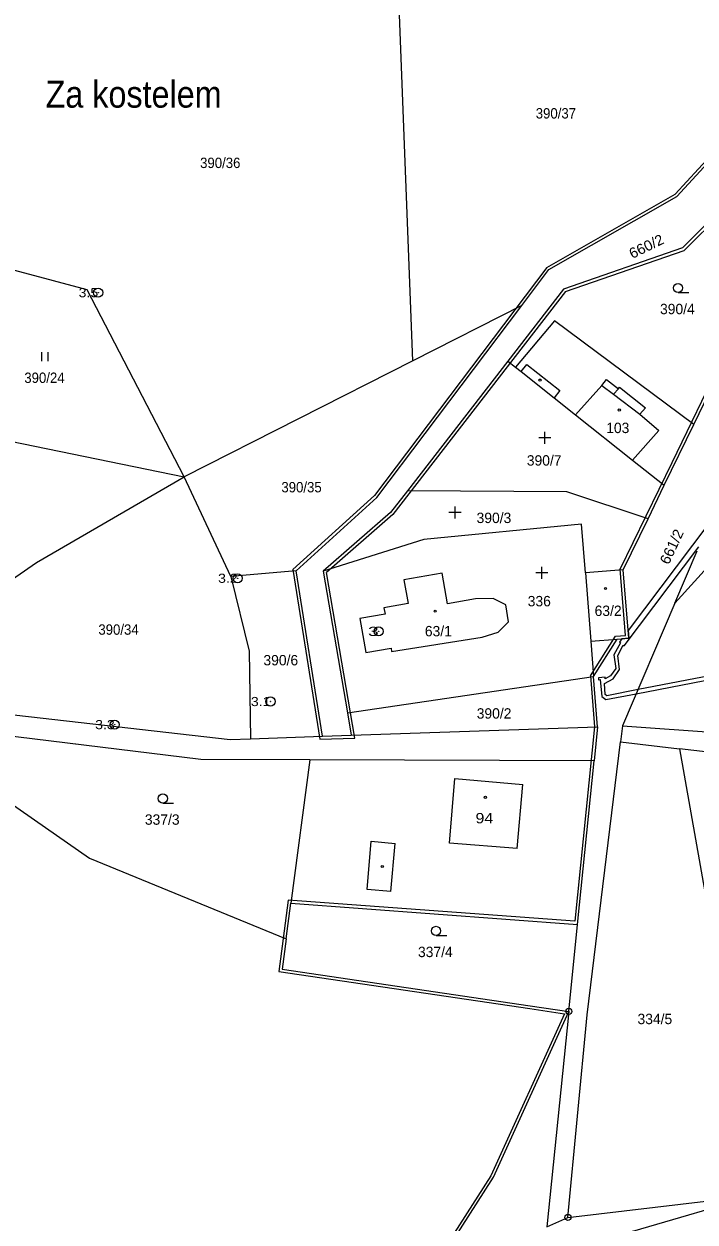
# Model space of a CAD drawing. Extents: x -758887 to -754328, y -1031688 to -1029144.
# Drawn here: x -756703.8 to -756593.9, y -1030846 to -1030649.6 of the extents above; entities that cross this region are included whole.
import ezdxf
from ezdxf.enums import TextEntityAlignment as Align

# ---------------------------------------------------------------- set-up
doc = ezdxf.new("R2010")
doc.units = 0
doc.header["$LTSCALE"] = 0.68
for name, color, linetype, lineweight in [('1', 7, 'Continuous', 25), ('13', 7, 'Continuous', 13), ('3', 7, 'Continuous', 25), ('4', 7, 'Continuous', 13), ('5', 7, 'Continuous', 25), ('7', 7, 'Continuous', 13), ('8', 7, 'Continuous', 25)]:
    doc.layers.add(name, color=color, linetype=linetype, lineweight=lineweight)
doc.layers.add('2', color=7, linetype='Continuous')

msp = doc.modelspace()

# ---------------------------------------------------------------- linework, layer by layer
at = {"layer": '1'}
for p, q in [((-756640.11, -1030704.83), (-756642.87, -1030632.93)), ((-756624.55, -1030704.88), (-756641.02, -1030726.18)), ((-756722.65, -1030714.62), (-756677.61, -1030723.85)), ((-756598.91, -1030725.25), (-756594.09, -1030715.3)), ((-756669.96, -1030740.2), (-756677.61, -1030723.85)), ((-756601.58, -1030730.76), (-756598.91, -1030725.25)), ((-756605.63, -1030739.13), (-756601.58, -1030730.76)), ((-756597.17, -1030744.56), (-756593.53, -1030736.02)), ((-756605.63, -1030739.13), (-756611.84, -1030739.62)), ((-756597.17, -1030744.56), (-756605.74, -1030764.66)), ((-756650.85, -1030762.53), (-756610.49, -1030756.62)), ((-756609.84, -1030764.83), (-756610.49, -1030756.62)), ((-756650.85, -1030762.53), (-756650.22, -1030766.22)), ((-756650.22, -1030766.22), (-756609.84, -1030764.83)), ((-756609.84, -1030764.83), (-756610.4, -1030770.41)), ((-756666.74, -1030766.79), (-756654.94, -1030766.38)), ((-756654.94, -1030766.38), (-756650.22, -1030766.22)), ((-756596.41, -1030768.46), (-756584.22, -1030837.68)), ((-756591.74, -1030769.01), (-756596.41, -1030768.46)), ((-756656.98, -1030770.25), (-756660.11, -1030793.78)), ((-756610.4, -1030770.41), (-756656.98, -1030770.25)), ((-756614.56, -1030811.5), (-756613.12, -1030797.27))]:
    msp.add_line(p, q, dxfattribs=at)
for points in [[(-756622.25, -1030695.77), (-756617.82, -1030689.9), (-756596.84, -1030677.93), (-756567.17, -1030645.53)], [(-756282.9, -1030655.55), (-756308.06, -1030668.02), (-756379, -1030674.01), (-756490.83, -1030676.79), (-756512.76, -1030685.59), (-756531.71, -1030701.08), (-756573.47, -1030723.47), (-756585.94, -1030732.18), (-756597.17, -1030744.56)], [(-756570.62, -1030661.18), (-756595.91, -1030686.32), (-756615.43, -1030693.08), (-756624.55, -1030704.88), (-756623.32, -1030705.86)], [(-756594.09, -1030715.3), (-756580.15, -1030686.52), (-756570.62, -1030661.18)], [(-756677.61, -1030723.85), (-756693.48, -1030693.18), (-756710.9, -1030688.54), (-756722.65, -1030714.62)], [(-756622.25, -1030695.77), (-756640.11, -1030704.83), (-756677.61, -1030723.85)], [(-756659.24, -1030739.27), (-756646.03, -1030727.27), (-756622.25, -1030695.77)], [(-756594.09, -1030715.3), (-756616.91, -1030698.28), (-756623.32, -1030705.86)], [(-756623.32, -1030705.86), (-756622.39, -1030706.6), (-756616.98, -1030710.89), (-756613.46, -1030713.69), (-756604.12, -1030721.11), (-756598.91, -1030725.25)], [(-756722.86, -1030752.48), (-756701.77, -1030737.88), (-756677.61, -1030723.85)], [(-756641.02, -1030726.18), (-756643.76, -1030729.72), (-756654.81, -1030739.33)], [(-756601.58, -1030730.76), (-756614.88, -1030726.31), (-756641.02, -1030726.18)], [(-756611.84, -1030739.62), (-756612.48, -1030731.64), (-756638.34, -1030734.14), (-756654.81, -1030739.33), (-756650.85, -1030762.53)], [(-756654.94, -1030766.38), (-756659.24, -1030739.27), (-756669.96, -1030740.2)], [(-756611.84, -1030739.62), (-756610.95, -1030750.82), (-756610.49, -1030756.62)], [(-756610.49, -1030756.62), (-756606.64, -1030750.47), (-756604.74, -1030750.32), (-756605.63, -1030739.13)], [(-756669.96, -1030740.2), (-756666.92, -1030752.42), (-756666.74, -1030766.79)], [(-756739.59, -1030766.99), (-756715.62, -1030761.72), (-756670.06, -1030766.9), (-756666.74, -1030766.79)], [(-756656.98, -1030770.25), (-756674.86, -1030770.19), (-756715.94, -1030765.19), (-756719.48, -1030766.11)], [(-756605.74, -1030764.66), (-756606.07, -1030767.32), (-756596.41, -1030768.46)], [(-756605.74, -1030764.66), (-756589.65, -1030765.83), (-756579.1, -1030774.93)], [(-756719.48, -1030766.11), (-756711.75, -1030773.45), (-756693.09, -1030786.36), (-756660.88, -1030799.59), (-756660.11, -1030793.78)], [(-756614.71, -1030845.27), (-756611.56, -1030812.04), (-756606.07, -1030767.32)], [(-756660.11, -1030793.78), (-756613.12, -1030797.27), (-756610.4, -1030770.41)], [(-756660.88, -1030799.59), (-756661.54, -1030804.55), (-756620.89, -1030810.56), (-756614.56, -1030811.5)], [(-756672.17, -1030908.07), (-756660.72, -1030891.63), (-756626.91, -1030838.7), (-756614.56, -1030811.5)], [(-756614.56, -1030811.5), (-756618.14, -1030846.79), (-756614.71, -1030845.27)], [(-756614.71, -1030845.27), (-756591.19, -1030842.49), (-756584.22, -1030837.68)], [(-756583.54, -1030841.59), (-756604.14, -1030847.6), (-756617.85, -1030857.11), (-756621.79, -1030861.59), (-756483.51, -1030902.61)]]:
    msp.add_lwpolyline(points, dxfattribs=at)
msp.add_lwpolyline([(-756628.75, -1030750.15), (-756626.15, -1030749.33), (-756624.43, -1030747.61), (-756624.89, -1030744.86), (-756626.95, -1030743.83), (-756629.84, -1030743.88), (-756634.44, -1030744.68), (-756635.32, -1030739.64), (-756641.59, -1030740.73), (-756640.91, -1030744.65), (-756644.85, -1030745.34), (-756644.67, -1030746.39), (-756648.81, -1030747.11), (-756647.84, -1030752.68), (-756643.7, -1030751.96), (-756643.61, -1030752.49)], close=True, dxfattribs=at)
at = {"layer": '13'}
for points in [[(-756591.62, -1030731.54), (-756604.84, -1030749.06), (-756604.74, -1030750.32), (-756605.85, -1030750.41), (-756606.27, -1030750.96), (-756606.11, -1030751.08), (-756607.16, -1030753.02), (-756606.88, -1030755.29), (-756607.72, -1030756.5), (-756608.6, -1030756.97), (-756608.63, -1030756.69), (-756609.72, -1030756.82), (-756609.69, -1030757.12), (-756609.45, -1030757.09), (-756609.17, -1030759.88), (-756608.48, -1030760.38), (-756603.5, -1030759.41), (-756588.59, -1030756.52)], [(-756588.65, -1030755.92), (-756603.22, -1030758.75), (-756608.34, -1030759.74), (-756608.59, -1030759.56), (-756608.72, -1030757.76), (-756607.3, -1030756.96), (-756606.26, -1030755.45), (-756606.54, -1030753.14), (-756605.63, -1030751.44), (-756605.47, -1030751.56), (-756593.25, -1030735.36)]]:
    msp.add_lwpolyline(points, dxfattribs=at)
at = {"layer": '3'}
for p, q in [((-756596.663, -1030693.65), (-756594.913, -1030693.65)), ((-756700.901, -1030704.92), (-756700.901, -1030703.42)), ((-756699.9, -1030704.92), (-756699.9, -1030703.42)), ((-756617.499, -1030717.471), (-756619.501, -1030717.471)), ((-756618.5, -1030718.47), (-756618.5, -1030716.47)), ((-756632.199, -1030729.701), (-756634.201, -1030729.701)), ((-756633.2, -1030730.7), (-756633.2, -1030728.7)), ((-756617.979, -1030739.591), (-756619.981, -1030739.591)), ((-756618.98, -1030740.59), (-756618.98, -1030738.59)), ((-756681.083, -1030777.35), (-756679.333, -1030777.35)), ((-756636.323, -1030799.05), (-756634.573, -1030799.05))]:
    msp.add_line(p, q, dxfattribs=at)
for centre in [(-756596.6629, -1030692.8998), (-756681.0829, -1030776.5998), (-756636.3229, -1030798.2998)]:
    msp.add_circle(centre, 0.75, dxfattribs=at)
at = {"layer": '4'}
for p, q in [((-756597.16, -1030677.54), (-756568.24, -1030645.96)), ((-756595.64, -1030686.75), (-756571.9, -1030663.15)), ((-756618.16, -1030689.52), (-756597.16, -1030677.54)), ((-756615.12, -1030693.5), (-756595.64, -1030686.75)), ((-756597.65, -1030721.5), (-756580.61, -1030686.32)), ((-756615.12, -1030693.5), (-756643.38, -1030730.05)), ((-756622.39, -1030706.6), (-756621.45, -1030705.43)), ((-756621.45, -1030705.43), (-756616.05, -1030709.72)), ((-756616.05, -1030709.72), (-756616.98, -1030710.89)), ((-756613.46, -1030713.69), (-756609.14, -1030708.87)), ((-756607.26, -1030710.33), (-756602.91, -1030713.58)), ((-756602.91, -1030713.58), (-756599.8, -1030716.29)), ((-756599.8, -1030716.29), (-756604.12, -1030721.11)), ((-756606.14, -1030739.02), (-756597.65, -1030721.5)), ((-756643.38, -1030730.05), (-756654.27, -1030739.52)), ((-756605.28, -1030749.86), (-756606.14, -1030739.02)), ((-756611, -1030756.49), (-756606.93, -1030749.99)), ((-756610.95, -1030750.82), (-756606.64, -1030750.47)), ((-756606.93, -1030749.99), (-756605.28, -1030749.86)), ((-756611, -1030756.49), (-756610.34, -1030764.85)), ((-756610.34, -1030764.85), (-756613.57, -1030796.73)), ((-756623.03, -1030784.81), (-756622.1, -1030774.3)), ((-756643.74, -1030791.83), (-756642.99, -1030783.96)), ((-756623.03, -1030784.81), (-756634.09, -1030783.92)), ((-756643.74, -1030791.83), (-756647.58, -1030791.54)), ((-756613.57, -1030796.73), (-756660.54, -1030793.25))]:
    msp.add_line(p, q, dxfattribs=at)
for points in [[(-756618.16, -1030689.52), (-756646.38, -1030726.91), (-756659.78, -1030739.08), (-756655.36, -1030766.89), (-756649.63, -1030766.7), (-756654.27, -1030739.52)], [(-756609.14, -1030708.87), (-756608.37, -1030707.91), (-756606.44, -1030709.41)], [(-756609.14, -1030708.87), (-756607.26, -1030710.33), (-756606.44, -1030709.41)], [(-756606.44, -1030709.41), (-756606.24, -1030709.19), (-756602, -1030712.56), (-756602.91, -1030713.58)], [(-756634.09, -1030783.92), (-756633.24, -1030773.31), (-756622.1, -1030774.3)], [(-756647.58, -1030791.54), (-756646.97, -1030783.58), (-756642.99, -1030783.96)], [(-756660.54, -1030793.25), (-756661.38, -1030799.52), (-756662.1, -1030804.97), (-756620.96, -1030811.05), (-756615.29, -1030811.9), (-756627.35, -1030838.46), (-756661.14, -1030891.35), (-756672.31, -1030907.39), (-756691.78, -1030895.26), (-756764.12, -1030846.63), (-756786.07, -1030837.87), (-756787.28, -1030837.13)]]:
    msp.add_lwpolyline(points, dxfattribs=at)
at = {"layer": '5'}
for centre in [(-756619.2768, -1030707.9992), (-756606.2868, -1030712.9092), (-756608.5568, -1030742.1792), (-756636.4668, -1030745.8892), (-756628.2368, -1030776.4092), (-756645.1268, -1030787.7392)]:
    msp.add_circle(centre, 0.175, dxfattribs=at)
at = {"layer": '8'}
for centre, radius in [((-756691.68, -1030693.6698), 0.75), ((-756691.68, -1030693.6698), 0.03), ((-756668.83, -1030740.4898), 0.75), ((-756668.83, -1030740.4898), 0.03), ((-756645.71, -1030749.1998), 0.75), ((-756645.71, -1030749.1998), 0.03), ((-756663.45, -1030760.6998), 0.75), ((-756663.45, -1030760.6998), 0.03), ((-756688.97, -1030764.4798), 0.75), ((-756688.97, -1030764.4798), 0.03), ((-756614.56, -1030811.4999), 0.5), ((-756614.56, -1030811.4999), 0.0303), ((-756614.71, -1030845.2699), 0.5), ((-756614.71, -1030845.2699), 0.0303)]:
    msp.add_circle(centre, radius, dxfattribs=at)

# ---------------------------------------------------------------- texts
at = {"layer": '2'}
for s, width, p in [('390/37', 0.95, (-756616.679, -1030665.12)), ('390/36', 0.95, (-756671.679, -1030673.24)), ('390/24', 0.95, (-756700.489, -1030708.47)), ('390/35', 0.95, (-756658.359, -1030726.41)), ('390/34', 0.95, (-756688.349, -1030749.75)), ('94', 1.15, (-756628.4, -1030780.67))]:
    msp.add_text(s, height=1.7, dxfattribs=dict(at, width=width)).set_placement(p, align=Align.CENTER)
at = {"layer": '2', "width": 1.05}
for s, rotation, p in [('660/2', 26, (-756601.4791, -1030686.8422)), ('661/2', 65, (-756596.9271, -1030735.6687))]:
    msp.add_text(s, height=1.7, rotation=rotation, dxfattribs=at).set_placement(p, align=Align.CENTER)
at = {"layer": '2'}
for s, p in [('390/4', (-756596.77, -1030697.2)), ('103', (-756606.539, -1030716.69)), ('390/7', (-756618.6, -1030722.02)), ('390/3', (-756626.83, -1030731.44)), ('336', (-756619.399, -1030745.09)), ('63/2', (-756608.12, -1030746.67)), ('63/1', (-756635.94, -1030750.01)), ('390/6', (-756661.76, -1030754.77)), ('390/2', (-756626.81, -1030763.5)), ('337/3', (-756681.19, -1030780.9)), ('337/4', (-756636.43, -1030802.6)), ('334/5', (-756600.46, -1030813.59))]:
    msp.add_text(s, height=1.7, dxfattribs=at).set_placement(p, align=Align.CENTER)
at = {"layer": '7', "width": 0.9}
msp.add_text('Za kostelem', height=4.4, dxfattribs=at).set_placement((-756685.879, -1030663.34), align=Align.CENTER)
at = {"layer": '8'}
for s, width, p in [('3.5', 1.15, (-756691.679, -1030694.42)), ('3.2', 1.15, (-756668.829, -1030741.24)), ('3', 1.6, (-756645.71, -1030749.95)), ('3.1', 1.15, (-756663.449, -1030761.45)), ('3.3', 1.15, (-756688.969, -1030765.23))]:
    msp.add_text(s, height=1.5, dxfattribs=dict(at, width=width)).set_placement(p, align=Align.RIGHT)

doc.saveas('drawing.dxf')
